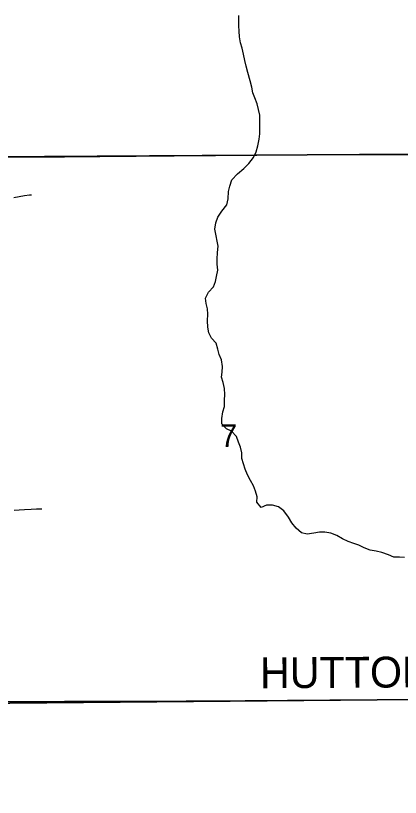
# Model space of a CAD drawing. Extents: x 1985906 to 2360102, y 891258 to 1222054.
# Drawn here: x 2109399 to 2113140, y 1045904 to 1053500 of the extents above; entities that cross this region are included whole.
import ezdxf

# ---------------------------------------------------------------- set-up
doc = ezdxf.new("R2010")
doc.units = 0
for name, color, linetype in [('GM_X_Minor_River', 7, 'Continuous'), ('GM_X_Section', 7, 'Continuous'), ('GM_X_Section_Text', 7, 'Continuous'), ('GM_X_Township_Road', 7, 'Continuous'), ('GM_X_Township_Road_Text', 7, 'Continuous')]:
    doc.layers.add(name, color=color, linetype=linetype)

msp = doc.modelspace()

# ---------------------------------------------------------------- linework, layer by layer
at = {"layer": 'GM_X_Minor_River'}
for points in [[(2111711.8, 1052122.1), (2111737.7, 1052176.2), (2111753.6, 1052236.4), (2111767.5, 1052300.6), (2111773.3, 1052352.7), (2111773.2, 1052410.9), (2111775.1, 1052469), (2111773, 1052531.2), (2111760.8, 1052589.3), (2111746.7, 1052641.4), (2111724.6, 1052699.6), (2111706.4, 1052749.7), (2111694.3, 1052803.8), (2111678.1, 1052867.9), (2111656, 1052948.1), (2111641.8, 1053008.3), (2111627.7, 1053062.4), (2111615.5, 1053124.5), (2111601.4, 1053182.7), (2111585.3, 1053234.8), (2111575.1, 1053294.9), (2111571, 1053349.1), (2111570.9, 1053401.2), (2111568.8, 1053451.3), (2111568.7, 1053501.4)], [(2113181.5, 1048233.8), (2113131.5, 1048239.7), (2113075.4, 1048239.7), (2113023.3, 1048261.7), (2112959.2, 1048283.6), (2112905.1, 1048295.6), (2112845, 1048305.6), (2112788.9, 1048327.6), (2112736.8, 1048353.6), (2112686.7, 1048371.6), (2112632.7, 1048389.6), (2112578.5, 1048415.6), (2112522.4, 1048447.6), (2112464.3, 1048471.6), (2112404.2, 1048481.5), (2112352.2, 1048481.5), (2112300.1, 1048471.4), (2112234.1, 1048461.3), (2112178, 1048475.3), (2112125.9, 1048519.3), (2112083.7, 1048571.4), (2112053.6, 1048627.5), (2112007.4, 1048687.6), (2111955.2, 1048727.7), (2111895.1, 1048743.7), (2111837.1, 1048743.6), (2111785.1, 1048719.5), (2111742.9, 1048773.6), (2111746.8, 1048825.7), (2111732.7, 1048879.8), (2111710.6, 1048929.9), (2111682.4, 1048982.1), (2111654.3, 1049038.2), (2111630.1, 1049094.3), (2111597.9, 1049198.5), (2111597.8, 1049250.6), (2111585.6, 1049306.8), (2111567.5, 1049356.9), (2111545.4, 1049411), (2111499.2, 1049463.1), (2111449.1, 1049485.1), (2111403, 1049535.1), (2111402.8, 1049585.3), (2111414.7, 1049649.5), (2111428.6, 1049703.6), (2111430.5, 1049763.8), (2111432.4, 1049819.9), (2111430.3, 1049876.1), (2111416.1, 1049934.2), (2111402, 1049986.3), (2111405.9, 1050036.4), (2111411.8, 1050090.6), (2111399.6, 1050154.7), (2111379.5, 1050208.8), (2111365.4, 1050259), (2111349.2, 1050317.1), (2111303.1, 1050367.2), (2111278.9, 1050419.3), (2111268.8, 1050473.4), (2111264.7, 1050535.6), (2111266.6, 1050599.7), (2111264.4, 1050649.8), (2111252.3, 1050704), (2111246.2, 1050756.1), (2111274.1, 1050812.3), (2111322, 1050864.4), (2111344, 1050916.6), (2111351.9, 1050966.8), (2111363.7, 1051026.9), (2111359.6, 1051085.1), (2111357.5, 1051135.2), (2111363.4, 1051199.3), (2111367.2, 1051259.5), (2111357.1, 1051309.6), (2111349, 1051359.8), (2111336.9, 1051425.9), (2111344.7, 1051488.1), (2111366.7, 1051540.2), (2111402.6, 1051600.4), (2111452.5, 1051660.6), (2111464.4, 1051718.8), (2111470.2, 1051791), (2111482.1, 1051843.1), (2111502, 1051903.3), (2111556, 1051961.5), (2111617.9, 1052013.7), (2111667.8, 1052063.9), (2111711.8, 1052122.1)], [(2109380.2, 1051732.6), (2109484.3, 1051752.7), (2109534.3, 1051758.8), (2109552.3, 1051758.8)], [(2109384.7, 1048694.8), (2109434.7, 1048696.9), (2109484.8, 1048701), (2109550.8, 1048705.1), (2109600.9, 1048709.1), (2109652.9, 1048709.2)]]:
    msp.add_lwpolyline(points, dxfattribs=at)
at = {"layer": 'GM_X_Section'}
for points in [[(2114287.5, 1057210), (2114277, 1052160.8), (2108655.6, 1052125.7), (2108578.1, 1057164.4), (2113883.3, 1057207.5)], [(2108655.6, 1052125.7), (2114277, 1052160.8), (2114343.5, 1046864.4), (2108626.2, 1046812.6), (2108654.8, 1051943.6)], [(2108626.2, 1046812.6), (2114343.5, 1046864.4), (2114352.9, 1041541.2), (2108607.2, 1041541.2), (2108623.2, 1046652.5)]]:
    msp.add_lwpolyline(points, close=True, dxfattribs=at)
at = {"layer": 'GM_X_Township_Road'}
for points in [[(2109120.1, 1052125.3), (2109431.7, 1052126.8), (2109873.9, 1052128.5), (2110052.9, 1052130.5), (2110217.5, 1052132.2), (2110316.3, 1052133.3), (2110572.7, 1052135.5), (2110693.3, 1052136.5), (2110939.2, 1052138.7), (2111742.8, 1052144.3), (2112005.2, 1052146.2), (2112431.3, 1052150.1), (2112599.8, 1052151.2), (2112907, 1052150.8), (2113923.9, 1052150.9)], [(2108641.4, 1046831.2), (2108706.9, 1046830.6), (2108845, 1046831.8), (2108940.2, 1046832), (2109026.4, 1046834), (2109220.6, 1046834.7), (2109402.3, 1046834.3), (2109551.4, 1046835.2), (2109759.9, 1046836.5), (2109875, 1046837.6), (2110203, 1046838.3), (2110547.6, 1046838.5), (2111056.6, 1046842.8), (2111631.5, 1046847), (2112452.6, 1046851.1), (2112698.9, 1046852), (2112895.7, 1046852.8), (2113158.1, 1046853.8), (2113371.1, 1046852.9), (2113878.9, 1046853.7), (2113964.6, 1046854), (2114239.3, 1046855.5), (2114337.4, 1046855.3)]]:
    msp.add_lwpolyline(points, dxfattribs=at)

# ---------------------------------------------------------------- texts
at = {"layer": 'GM_X_Section_Text'}
msp.add_text('7', height=221, rotation=0.00001, dxfattribs=at).set_placement((2111388.9, 1049308.7))
at = {"layer": 'GM_X_Township_Road_Text'}
msp.add_text('HUTTON', height=300, rotation=0.32453, dxfattribs=at).set_placement((2111775.7, 1046964.2))

doc.saveas('drawing.dxf')
